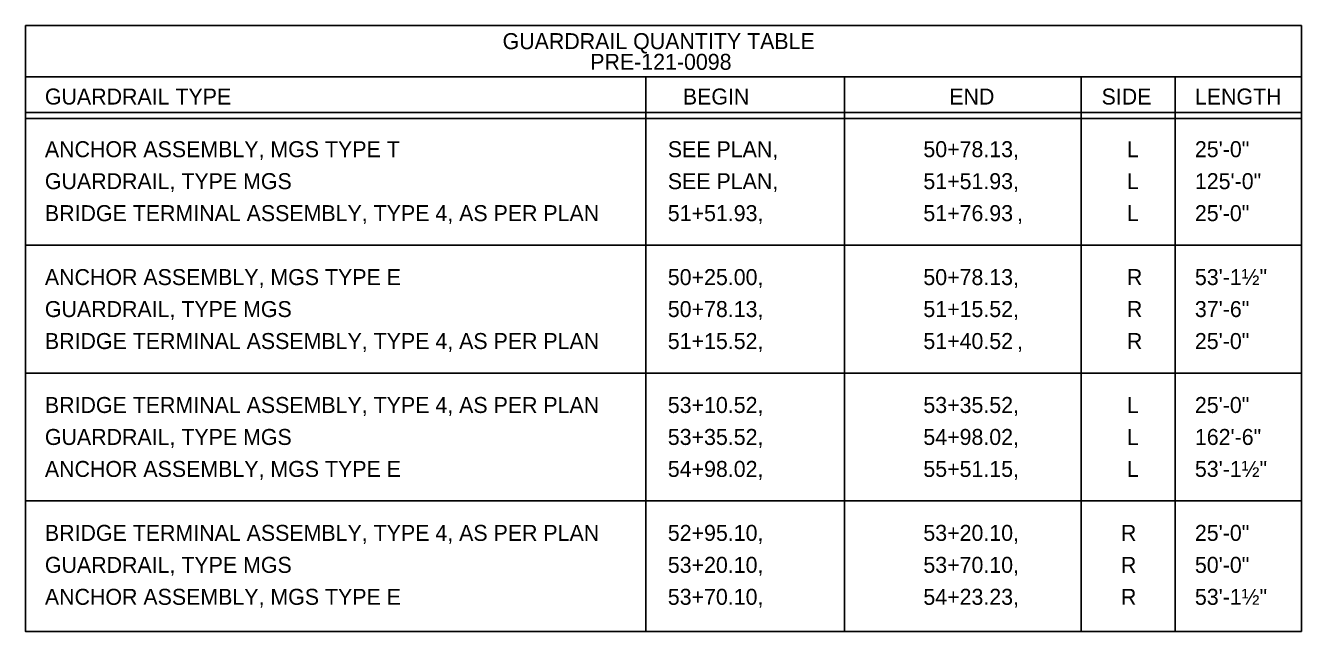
# Model space of a CAD drawing. Extents: x -27.3 to 69.3, y 0 to 30.
# Drawn here: x -23.52 to -12.33, y 3.68 to 8.99 of the extents above; entities that cross this region are included whole.
import ezdxf

# ---------------------------------------------------------------- set-up
doc = ezdxf.new("R2010")
doc.units = 0
doc.layers.add('SH_Data', color=7, linetype='Continuous')
doc.layers.add('SH_Text', color=7, linetype='Continuous')

msp = doc.modelspace()

# ---------------------------------------------------------------- linework, layer by layer
at = {"layer": 'SH_Text'}
for p, q in [((-23.518, 8.537), (-12.334, 8.537)), ((-18.081, 8.537), (-18.081, 3.681)), ((-16.339, 8.537), (-16.339, 3.681)), ((-14.264, 8.537), (-14.264, 3.681)), ((-13.442, 8.537), (-13.442, 3.681)), ((-23.518, 8.224), (-12.334, 8.224)), ((-23.518, 8.174), (-12.334, 8.174)), ((-23.518, 7.064), (-12.334, 7.064)), ((-23.518, 5.944), (-12.334, 5.944)), ((-23.518, 4.824), (-12.334, 4.824))]:
    msp.add_line(p, q, dxfattribs=at)
msp.add_lwpolyline([(-23.518, 8.987), (-12.334, 8.987), (-12.334, 3.681), (-23.518, 3.681)], close=True, dxfattribs=at)

# ---------------------------------------------------------------- texts
at = {"layer": 'SH_Data'}
for s, p in [('GUARDRAIL QUANTITY TABLE', (-19.336, 8.78)), ('PRE-121-0098', (-18.568, 8.599))]:
    msp.add_text(s, height=0.14, dxfattribs=at).set_placement(p)
at = {"layer": 'SH_Text'}
for s, p in [('GUARDRAIL TYPE', (-23.348, 8.295)), ('BEGIN', (-17.756, 8.295)), ('END', (-15.421, 8.295)), ('SIDE', (-14.086, 8.295)), ('LENGTH', (-13.268, 8.295)), ('ANCHOR ASSEMBLY, MGS TYPE T ', (-23.348, 7.834)), ('SEE PLAN,', (-17.888, 7.834)), ('50+78.13,', (-15.648, 7.834)), ('  L', (-13.968, 7.834)), ('25\'-0"', (-13.268, 7.834)), ('GUARDRAIL, TYPE MGS ', (-23.348, 7.554)), ('SEE PLAN,', (-17.888, 7.554)), ('51+51.93,', (-15.648, 7.554)), ('  L', (-13.968, 7.554)), ('125\'-0"', (-13.268, 7.554)), ('BRIDGE TERMINAL ASSEMBLY, TYPE 4, AS PER PLAN ', (-23.348, 7.274)), ('51+51.93,', (-17.888, 7.274)), ('51+76.93', (-15.648, 7.274)), ('  L', (-13.968, 7.274)), ('25\'-0"', (-13.268, 7.274)), (',', (-14.827, 7.274)), ('ANCHOR ASSEMBLY, MGS TYPE E ', (-23.348, 6.714)), ('50+25.00,', (-17.888, 6.714)), ('50+78.13,', (-15.648, 6.714)), ('  R', (-13.968, 6.714)), ('53\'-1½"', (-13.268, 6.714)), ('GUARDRAIL, TYPE MGS ', (-23.348, 6.434)), ('50+78.13,', (-17.888, 6.434)), ('51+15.52,', (-15.648, 6.434)), ('  R', (-13.968, 6.434)), ('37\'-6"', (-13.268, 6.434)), ('BRIDGE TERMINAL ASSEMBLY, TYPE 4, AS PER PLAN ', (-23.348, 6.154)), ('51+15.52,', (-17.888, 6.154)), ('51+40.52', (-15.648, 6.154)), ('  R', (-13.968, 6.154)), ('25\'-0"', (-13.268, 6.154)), (',', (-14.827, 6.154)), ('BRIDGE TERMINAL ASSEMBLY, TYPE 4, AS PER PLAN ', (-23.348, 5.594)), ('53+10.52,', (-17.888, 5.594)), ('53+35.52,', (-15.648, 5.594)), ('  L', (-13.968, 5.594)), ('25\'-0"', (-13.268, 5.594)), ('GUARDRAIL, TYPE MGS ', (-23.348, 5.314)), ('53+35.52,', (-17.888, 5.314)), ('54+98.02,', (-15.648, 5.314)), ('  L', (-13.968, 5.314)), ('162\'-6"', (-13.268, 5.314)), ('ANCHOR ASSEMBLY, MGS TYPE E ', (-23.348, 5.034)), ('54+98.02,', (-17.888, 5.034)), ('55+51.15,', (-15.648, 5.034)), ('  L', (-13.968, 5.034)), ('53\'-1½"', (-13.268, 5.034)), ('BRIDGE TERMINAL ASSEMBLY, TYPE 4, AS PER PLAN ', (-23.348, 4.474)), ('52+95.10,', (-17.888, 4.474)), ('53+20.10,', (-15.648, 4.474)), (' R', (-13.968, 4.474)), ('25\'-0"', (-13.268, 4.474)), ('GUARDRAIL, TYPE MGS ', (-23.348, 4.194)), ('53+20.10,', (-17.888, 4.194)), ('53+70.10,', (-15.648, 4.194)), (' R', (-13.968, 4.194)), ('50\'-0"', (-13.268, 4.194)), ('ANCHOR ASSEMBLY, MGS TYPE E ', (-23.348, 3.914)), ('53+70.10,', (-17.888, 3.914)), ('54+23.23,', (-15.648, 3.914)), (' R', (-13.968, 3.914)), ('53\'-1½"', (-13.268, 3.914))]:
    msp.add_text(s, height=0.14, rotation=360, dxfattribs=at).set_placement(p)

doc.saveas('drawing.dxf')
